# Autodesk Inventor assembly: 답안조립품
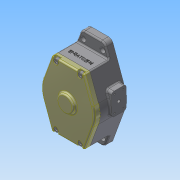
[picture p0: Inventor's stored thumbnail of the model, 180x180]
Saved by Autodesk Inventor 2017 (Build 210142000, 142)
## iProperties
Part Number: 답안조립품
Material: 일반
Document SubType Name: Assembly
Designer: Administrator
Author: Administrator
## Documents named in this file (14)
- C:\Users\Administrator\Desktop\731106V1002\답안조립품.iam
- C:\Users\Administrator\Desktop\731106V1002\본체.ipt
- C:\Users\Administrator\Desktop\731106V1002\오일 실 14 25 4.ipt
- C:\Users\Administrator\Desktop\731106V1002\축.ipt
- C:\Users\Administrator\Desktop\731106V1002\평행 키 5x5x22.ipt
- C:\Users\Administrator\Desktop\731106V1002\오일레스 부시.ipt
- C:\Users\Administrator\Desktop\731106V1002\DU 부시.ipt
- C:\Users\Administrator\Desktop\731106V1002\내접기어.ipt
- C:\Users\Administrator\Desktop\731106V1002\스퍼기어.ipt
- C:\Users\Administrator\Desktop\731106V1002\크레센트.ipt
- C:\Users\Administrator\Desktop\731106V1002\육각 소켓 머리 볼트 M4 x 30.ipt
- C:\Users\Administrator\Desktop\731106V1002\O링 G90.ipt
- C:\Users\Administrator\Desktop\731106V1002\육각 소켓 머리 볼트 M6 x 12.ipt
- C:\Users\Administrator\Desktop\731106V1002\커버.ipt
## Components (2 placed, 2 different names)
1. DU 부시:1
2. O링 G90:1
